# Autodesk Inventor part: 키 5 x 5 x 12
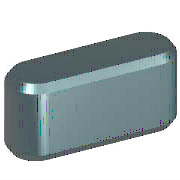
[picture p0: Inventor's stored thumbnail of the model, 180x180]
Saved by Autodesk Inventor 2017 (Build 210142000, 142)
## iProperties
Created: 2012-02
Part Number: 키 5 x 5 x 12
Material: 강철, 연강
Description: 키 및 해당 키홈
Document SubType Name: Modeling
Standard: KS B 1311
Designer: mduedu
Standards Organization: KS
Language: ko-KR
Size Designation: 5 x 5 x 12
Categories: <MemberInstance><Categories><Category DisplayName="샤프트 부품" InternalName="7f7aeb1f-a693-4053-b835-cee3144e0d98" Mnemonic="SHFT"><Category DisplayName="키" Interna
Density: 7.85 g/cm^3
Appearance: 노란색
Mass: 2.10816 g
Surface Area: 2.43471 cm^2
Volume: 0.268556 cm^3
IsCustomPart: 1
Author: mduedu
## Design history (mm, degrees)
workplane "Work Plane1"
workplane "Work Plane2"
sketch "스케치1"
  geometry: L1 (2.5, 2.5)-(9.5, 2.5); L2 (9.5, -2.5)-(2.5, -2.5); L3 (0, 9.4)-(0, -7.4) reference; L4 (-5, 0)-(30, 0) reference; L5 (12, 0)-(12, 7); A1 r 2.5 centre (2.5, 0) between (2.5, 2.5) and (2.5, -2.5); A2 r 2.5 centre (9.5, 0) between (9.5, -2.5) and (9.5, 2.5)
  constraints: 6 end point, 5 point on circle, 4 tangent, 3 point on line, 2 centre point, 1 horizontal, 1 parallel, 1 perpendicular
  dimensions: "d0" = 2.5 radius of A1 (= 0.5 x PB); "d13" = 2.5 radius of A2 (= 0.5 x PB); "d14" = 12 distance between parallel lines of L5 L3 (= NLG)
extrude "본체1" new body sketch "스케치1" taper "d3" = 0 deg; stored distance "d4" = 10
workplane "Work Plane3"
body "Solid1"
chamfer "모따기1" distance "d8" = 0.4 (= PHH); stored, may be unused: second distance "d9" = 0.4 (= PHH), angle "d15" = 45 deg
other parameters: "d1" = -3 (= -PNT), "d2" = 2 (= PH - PNT), "NLG" = 12 [user parameter; used in 3 equation terms], "PB" = 5 [user parameter; used in 2 equation terms], "PNT" = 3 [user parameter; used in 2 equation terms], "PH" = 5 [user parameter; used in 1 equation term], "PHH" = 0.4 [user parameter; used in 2 equation terms], "d10" = 0, "d16" = 0, "d17" = 0, "d18" = 0, "WDMIN" = 12 [user parameter], "PLB2" = 12 (= NLG) [user parameter], "WDMAX" = 17 [user parameter], "PLB1" = 12 (= NLG) [user parameter], "RR" = 0.16 [user parameter], "PUEB" = 2.3 [user parameter]
